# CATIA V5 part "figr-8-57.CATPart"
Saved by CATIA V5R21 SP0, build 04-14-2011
Part number: Part1
Bounding box of the stored display mesh (mm): x -50.499 to 50.499, y -68.48 to 68.48, z -46 to 50
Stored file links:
  D:\CATIA V5R21 E-RESOURCES\CATIA-V5R21\catia-v5r21-prt\c08-catia-v5r20-prt\c08-catia-v5r21-figr-8-57.CATPart
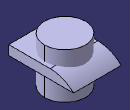
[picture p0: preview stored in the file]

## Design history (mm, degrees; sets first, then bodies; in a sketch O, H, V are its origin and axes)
Body1 (main body)
  Sketch1 on xy-plane, origin (0, 0, 0), H (1, 0, 0), V (0, 1, 0)
    line L1 (-50.499, 68.4797) -> (50.499, 68.4797)
    line L2 (50.499, 68.4797) -> (50.499, -68.4797)
    line L3 (50.499, -68.4797) -> (-50.499, -68.4797)
    line L4 (-50.499, -68.4797) -> (-50.499, 68.4797)
    axis line L5 (50.499, -68.4797) -> (-50.499, 68.4797)
    horizontal: L1 H, L3 H
    vertical: L2 V, L4 V
    midpoint: O L5
  Pad1: profile Sketch1, direction (0, 0, 1), length 20
  Fillet1: radius 71, on edge [face of Pad1 | face of Pad1]
Body2
  Sketch2 on xy-plane, origin (0, 0, 0), H (1, 0, 0), V (0, 1, 0)
    circle A1 centre (0, 0) radius 43.2524
    point P1 (0, 43.2524)
    coincidence: A1 P1, P1 V
  Pad2: profile Sketch2, direction (0, 0, 1), length 50, opposite side length 46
